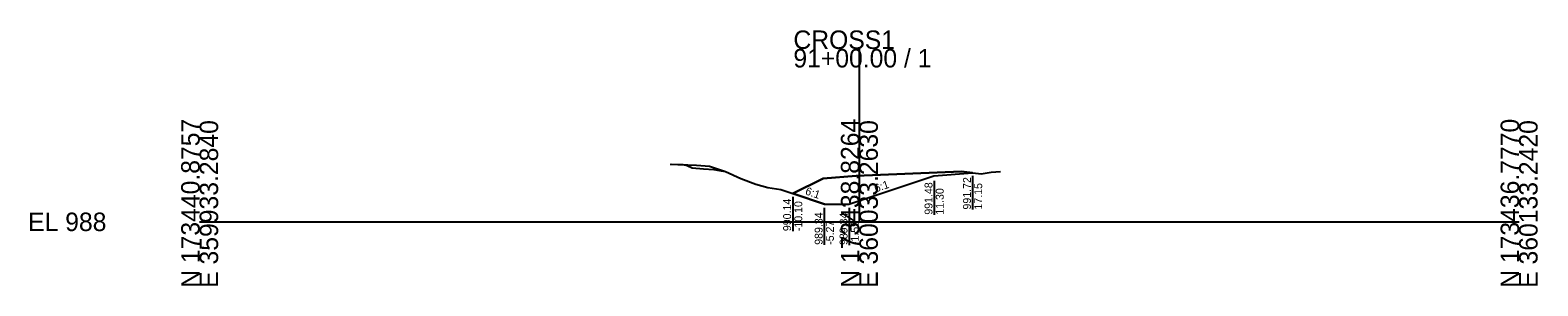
# Model space of a CAD drawing. Extents: x -26 to 1403, y -10 to 11027.
# Drawn here: x -25.7 to 202.8, y 5990.3 to 6029 of the extents above; entities that cross this region are included whole.
import ezdxf

# ---------------------------------------------------------------- set-up
doc = ezdxf.new("R2010")
doc.units = 0
for name, color, linetype in [('Default', 7, 'Continuous'), ('P_E_XS_Ground', 7, 'Continuous'), ('P_XS', 7, 'Continuous'), ('P_XS_EAR_CommonGrnd', 7, 'Continuous'), ('P_XS_Lane', 7, 'Continuous'), ('P_XS_Rock', 7, 'Continuous')]:
    doc.layers.add(name, color=color, linetype=linetype)

msp = doc.modelspace()

# ---------------------------------------------------------------- linework, layer by layer
at = {"layer": 'Default'}
for p, q in [((100, 6000), (100, 6026.18)), ((0, 6000), (100, 6000)), ((100, 6000), (200, 6000))]:
    msp.add_line(p, q, dxfattribs=at)
at = {"layer": 'P_E_XS_Ground'}
for p, q in [((71.46, 6008.73), (72.49, 6008.66)), ((72.49, 6008.66), (73.26, 6008.66)), ((73.26, 6008.66), (73.91, 6008.52)), ((73.91, 6008.52), (74.63, 6008.18)), ((74.63, 6008.18), (76.38, 6008.05)), ((76.38, 6008.05), (77.94, 6007.9)), ((77.94, 6007.9), (79.06, 6007.73)), ((79.06, 6007.73), (79.69, 6007.64)), ((79.69, 6007.64), (82.04, 6006.58)), ((82.04, 6006.58), (84.31, 6005.69)), ((89.9, 6004.28), (94.5, 6006.58)), ((94.5, 6006.58), (99.5, 6006.98)), ((99.5, 6006.98), (115.5, 6007.62)), ((115.5, 6007.62), (118.47, 6007.28)), ((118.47, 6007.28), (119.96, 6007.5)), ((119.96, 6007.5), (121.39, 6007.61)), ((84.31, 6005.69), (86.12, 6005.21)), ((86.12, 6005.21), (88.07, 6004.88)), ((88.07, 6004.88), (89.9, 6004.28))]:
    msp.add_line(p, q, dxfattribs=at)
at = {"layer": 'P_XS'}
for p, q in [((71.3, 6008.73), (75.3, 6008.57)), ((75.3, 6008.57), (77.3, 6008.41)), ((77.3, 6008.41), (79.55, 6007.66))]:
    msp.add_line(p, q, dxfattribs=at)
at = {"layer": 'P_XS_EAR_CommonGrnd'}
msp.add_lwpolyline([(111.3, 6006.97), (117.15, 6007.43), (115.5, 6007.62), (99.5, 6006.98), (94.5, 6006.58), (89.9, 6004.28), (94.73, 6002.67), (98.41, 6002.67)], close=True, dxfattribs=at)
at = {"layer": 'P_XS_Lane'}
for p, q in [((98.41, 6002.67), (111.3, 6006.97)), ((111.3, 6006.97), (117.15, 6007.43)), ((94.73, 6002.67), (89.9, 6004.28)), ((94.73, 6002.67), (98.41, 6002.67))]:
    msp.add_line(p, q, dxfattribs=at)
at = {"layer": 'P_XS_Rock'}
for p, q in [((111.33, 6006.2), (111.33, 6001.08)), ((117.16, 6006.98), (117.16, 6001.86)), ((89.89, 6003.81), (89.89, 5998.59)), ((94.68, 6002.13), (94.68, 5996.52)), ((98.45, 6002.1), (98.45, 5996.48))]:
    msp.add_line(p, q, dxfattribs=at)

# ---------------------------------------------------------------- texts
at = {"layer": 'Default'}
for s, p in [('CROSS1', (90, 6026.18)), ('91+00.00 / 1', (90, 6023.38)), ('EL 988', (-26, 5998.6))]:
    msp.add_text(s, height=2.8, dxfattribs=at).set_placement(p)
for s, p in [('N 173440.8757', (0, 5990)), ('E 359933.2840', (2.8, 5990)), ('N 173438.8264', (100, 5990)), ('E 360033.2630', (102.8, 5990)), ('N 173436.7770', (200, 5990)), ('E 360133.2420', (202.8, 5990))]:
    msp.add_text(s, height=2.8, rotation=90, dxfattribs=at).set_placement(p)
at = {"layer": 'P_XS_Rock'}
for s, rotation, p in [('6:1', 18.4349, (102.49, 6004.46)), ('991.48', 90, (111.08, 6001.08)), ('991.72', 90, (116.91, 6001.86)), ('6:1', 341.5651, (91.7, 6004.17)), ('11.30', 90, (112.78, 6001.08)), ('17.15', 90, (118.61, 6001.86)), ('990.14', 90, (89.64, 5998.59)), ('-10.10', 90, (91.34, 5998.59)), ('989.34', 90, (94.43, 5996.52)), ('989.34', 90, (98.2, 5996.48)), ('-5.27', 90, (96.13, 5996.52)), ('-1.59', 90, (99.9, 5996.48))]:
    msp.add_text(s, height=1.2, rotation=rotation, dxfattribs=at).set_placement(p)

doc.saveas('drawing.dxf')
